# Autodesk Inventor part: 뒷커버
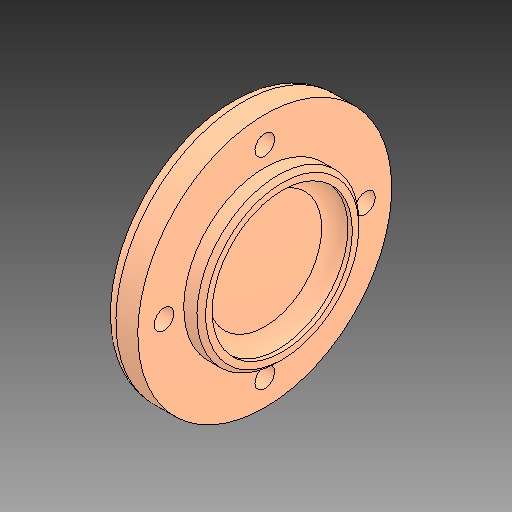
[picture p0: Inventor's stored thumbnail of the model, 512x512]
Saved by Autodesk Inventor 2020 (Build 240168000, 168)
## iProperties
Created: 2025-02
Part Number: 뒷커버
Material: 일반
Document SubType Name: Modeling
Designer: 1강의실14
Density: 1 g/cm^3
Appearance: 기본값
Author: jhkim
Sending System: Autodesk Inventor 2025
Preprocessor: ST-DEVELOPER v20
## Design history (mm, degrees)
feature "솔리드1"
node "솔리드2"
